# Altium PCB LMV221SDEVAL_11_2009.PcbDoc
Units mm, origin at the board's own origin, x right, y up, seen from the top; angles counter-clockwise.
Board outline 50.9 x 56.16 mm, 2 copper layers (Top Layer, Bottom Layer); 19 components, 8 nets, 54 pads, 66 vias.
Unrouted connection lines stored in the file: 8.
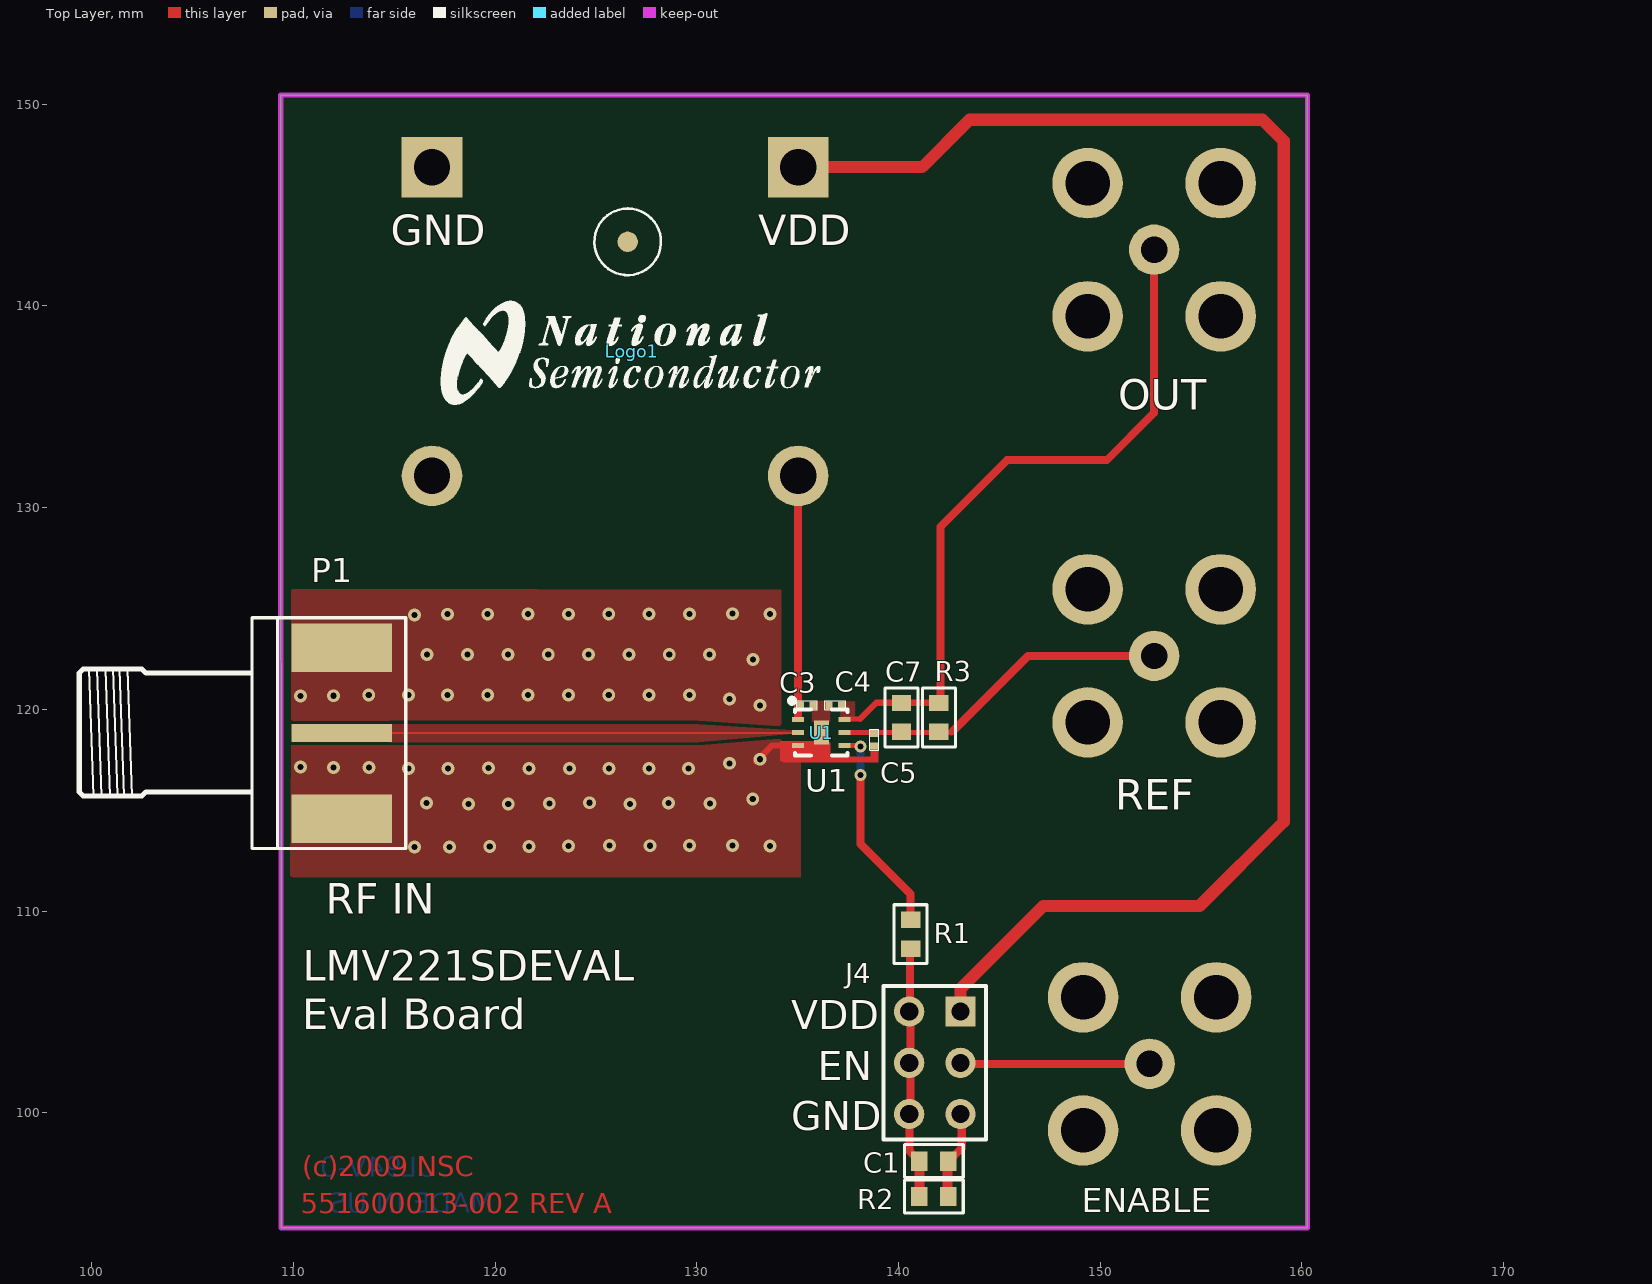
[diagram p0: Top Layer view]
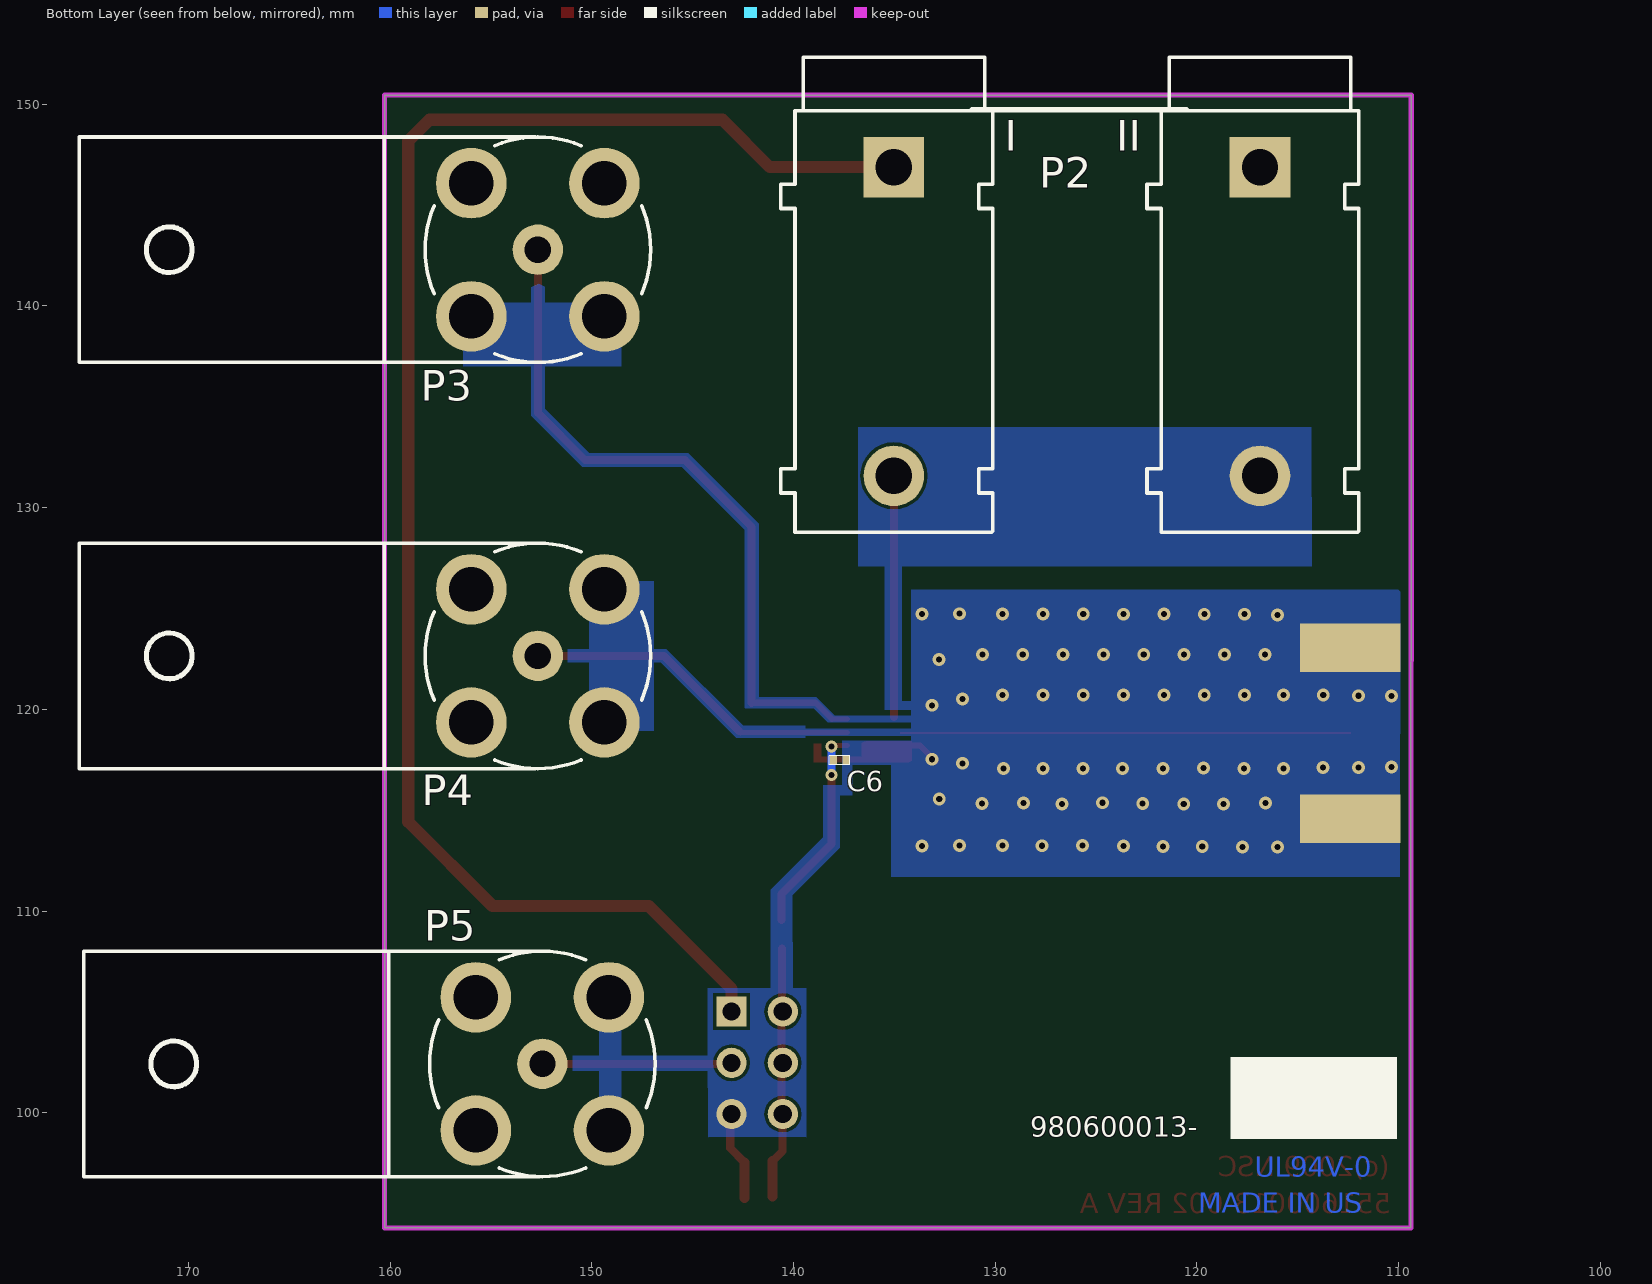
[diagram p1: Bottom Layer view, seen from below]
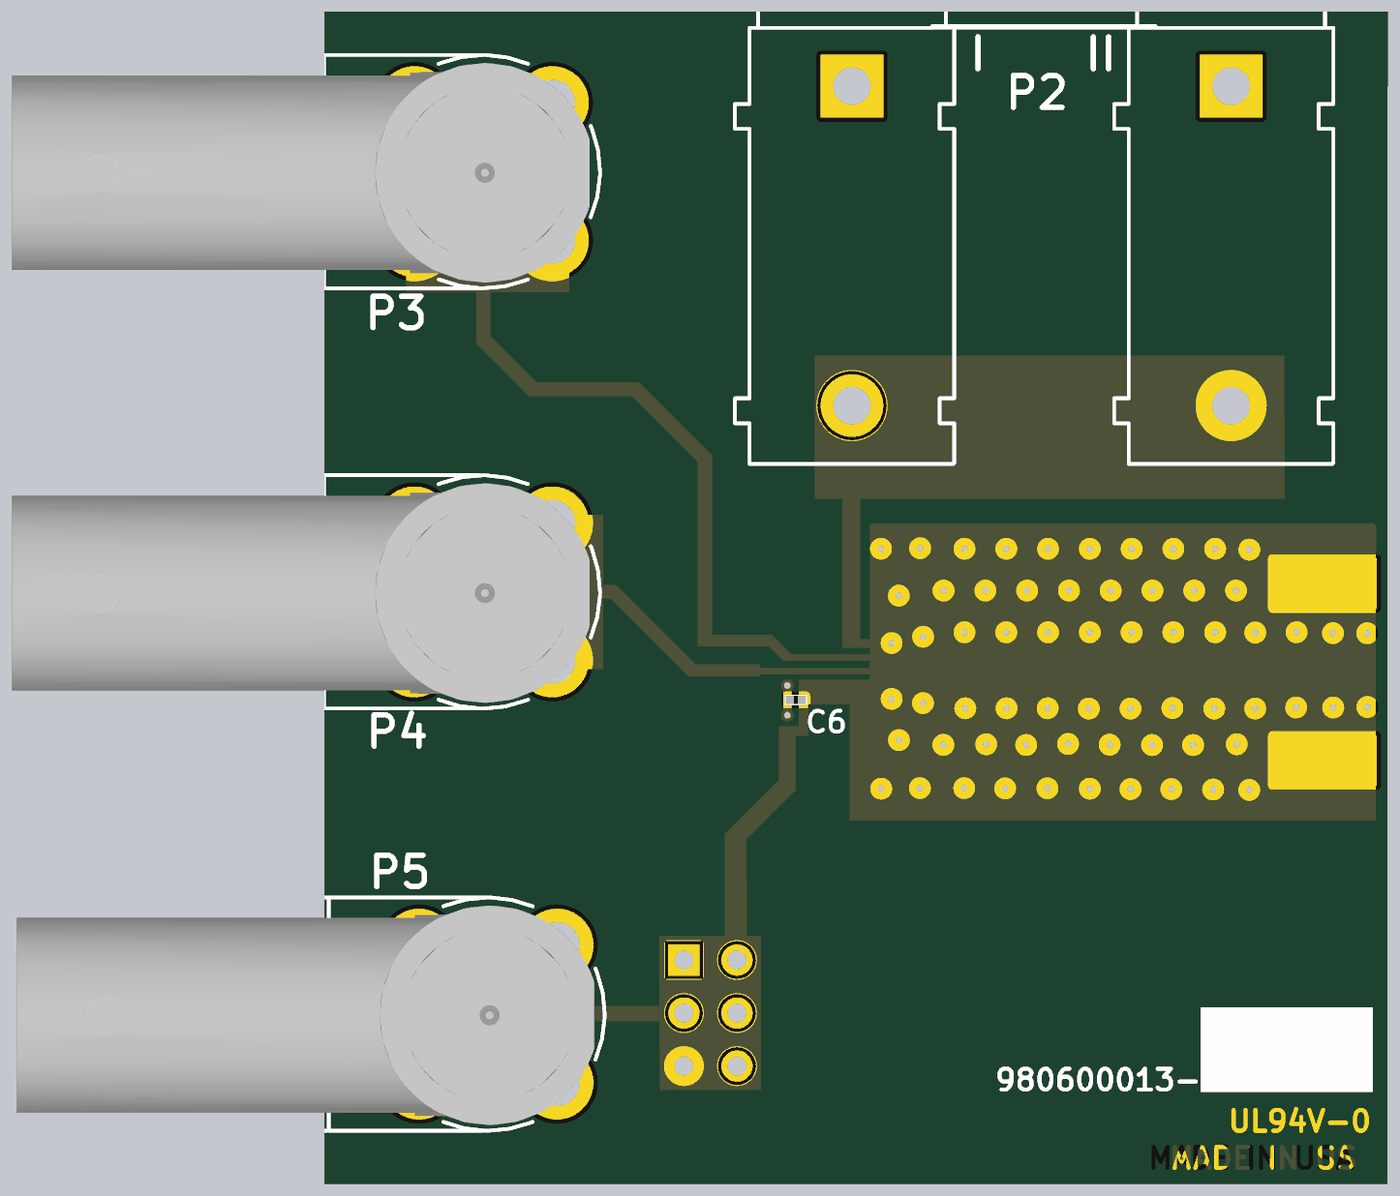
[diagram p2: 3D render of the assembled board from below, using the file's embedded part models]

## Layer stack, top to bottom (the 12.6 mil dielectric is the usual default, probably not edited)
Top Layer: signal copper 0.0356
Dielectric: core 0.32, FR-4, Dk 4.8
Bottom Layer: signal copper 0.0356

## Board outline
109.394,94.288 109.377,150.452 160.275,150.452 160.275,94.288

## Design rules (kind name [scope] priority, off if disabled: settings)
Clearance Clearance_4 [OnLayer('Mid-Layer 2') And (IsThruPin Or IsSMTPin Or IsWire) vs OnLayer('Mid-Layer 2') And (IsThruPin Or IsSMTPin Or IsWire Or IsVia)] p1: gap=0.01
Clearance Clearance_3 [OnLayer('Mid-Layer 1') And (IsThruPin Or IsSMTPin Or IsWire) vs OnLayer('Mid-Layer 1') And (IsThruPin Or IsSMTPin Or IsWire Or IsVia)] p2: gap=0.01
Clearance Clearance_2 [OnLayer('Bottom Layer') And (IsThruPin Or IsSMTPin Or IsWire) vs OnLayer('Bottom Layer') And (IsThruPin Or IsSMTPin Or IsWire Or IsVia)] p3: gap=0.15
Clearance Clearance_1 [OnLayer('Top Layer') And (IsThruPin Or IsSMTPin Or IsWire Or IsVia) vs OnLayer('Top Layer') And (IsThruPin Or IsSMTPin Or IsWire Or IsVia)] p4: gap=0.15
Clearance [All] p5: gap=0.152
PasteMaskExpansion [All] p1: expansion=0.051
PlaneConnect [All] p1: planeconnectstyle=Relief reliefexpansion=1 reliefentries=4 reliefconductorwidth=1 reliefairgap=0.8
PolygonConnect [All] p1: connectstyle=Direct reliefconductorwidth=0.254 reliefentries=4 polygonreliefangle="90 Angle"
RoomDefinition LMV221SDEVAL_11_2009 [InComponentClass('LMV221SDEVAL_11_2009')] p1: confinementstyle=ConfineIn formatcopy=TRUE lockcomponents=FALSE outline 161.404,93.156 168.804,93.156 168.804,115.308 161.404,115.308
RoutingVias [All] p1: holewidth=0.711 width=1.27 viastyle="Through Hole" minholewidth=0.711 minwidth=1.27 maxholewidth=0.711 maxwidth=1.27
SilkscreenOverComponentPads [All] p1: minsilkscreentomaskgap=0.254
SolderMaskExpansion [All] p1: expansion=0.203
TestPointUsage [All] p1: valid=0 allowmultiple=FALSE
Testpoint [All] p1: side=15 testpointundercomponent=TRUE minsize=1.016 maxsize=2.54 preferedsize=1.524 minholesize=0 maxholesize=1.016 preferedholesize=0.813 testpointgrid=0.025 style=1023 order=0123456789
Width Net_Width_1 [InNet('GND') Or InNet('N09047') Or InNet('N13699') Or InNet('N14327') Or InNet('N15309')] p1: maxlimit=2 minlimit=0.2 preferedwidth=0.2
Width [All] p2: maxlimit=2.007 minlimit=0.203 preferedwidth=0.203
21 further rules are at their usual default settings.

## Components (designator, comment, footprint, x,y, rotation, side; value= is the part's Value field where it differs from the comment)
C1 "10n" SM/RC_0603 141.75,97.6 r180 top
C3 "10p" C_SMD_201 135.475,120.2 r180 top
C4 "10p" C_SMD_201 136.85,120.2 r0 top
C5 "1p" C_SMD_201 138.8,118.5 r270 top
C6 "10p" C_SMD_201 137.7,117.475 r0 bottom
C7 "NC" SM/RC_0603 140.15,119.6 r90 top
I "571-0500" 571-0500 135.025,139.225 r270 bottom
II "571-0100" 571-0100 116.875,139.225 r270 bottom
J4 "Header 3x2" HDR2X3 141.8,102.475 r270 top
Logo1 "PCB Logo" Logo_Overlay_Medium 126.775,137.75 r0 top
P1 "RF IN" SMA-SIDE 112.4,118.825 r0 top
P3 "Vout" 5413631-2 152.674,142.784 r180 bottom
P4 "REF" 5413631-2 152.675,122.65 r180 bottom
P5 "Enable" 5413631-2 152.45,102.425 r180 bottom
R1 "100k" SM/RC_0603 140.6,108.85 r270 top
R2 "100k" SM/RC_0603 141.75,95.85 r180 top
R3 "NC" SM/RC_0603 142,119.6 r90 top
U1 "LLP6 LMV221" SDB06A 136.175,118.85 r270 top
? "Comment" Fiducial 126.575,143.175 r0 top

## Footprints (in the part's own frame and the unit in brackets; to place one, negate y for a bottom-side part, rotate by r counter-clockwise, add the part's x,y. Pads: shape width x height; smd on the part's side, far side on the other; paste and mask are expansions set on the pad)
571-0100 [mm] "Deltron Emcon recommended land pattern 2003-10-13"
  rect 3x3 hole 1.8: 1(-7.65,0)
  round 3 hole 1.8: 2(7.65,0)
  silkscreen extent -13.1,-5.6 10.45,4.9, body extent -13.04,-5.6 10.54,4.9, height 12.4
571-0500 [mm] "Deltron Emcon recommended land pattern 2003-10-13"
  rect 3x3 hole 1.8: 1(-7.65,0)
  round 3 hole 1.8: 2(7.65,0)
  silkscreen extent -13.1,-5.6 10.45,4.9, body extent -13.04,-5.6 10.54,4.9, height 12.4
5413631-2 [mm] "BNC footprint for Tyco_5413631"
  round 2.5 hole 1.3: 1(0,0)
  round 3.5 hole 2.2: 2(-3.3,3.3) 3(3.3,3.3) 4(3.3,-3.3) 5(-3.3,-3.3)
  Top Layer lines w0.05: 3.3,3.3 3.3,3.3
  silkscreen extent -22.73,-5.59 5.59,5.59, body extent -22.56,-5.27 5.08,5.16, height 11.66
C_SMD_201 [mm] "Chip Capacitor, 2-Leads, Body 0.6x0.3mm, IPC Medium Density"
  rect 0.35x0.4 smd: 1(-0.3,0) 2(0.325,0)
  silkscreen extent -0.5,-0.23 0.53,0.23, body extent -0.3,-0.16 0.31,0.15, height 0.02
Fiducial [mil]
  round 40 smd mask+40: 0(0,0)
  Top Overlay keep-out lines w5: 64.68,6.47 ccw(c0,0) 64.81,4.99
  silkscreen extent -65,-65 65,65
HDR2X3 [mm]
  rect 1.5x1.5 hole 0.9: 1(-2.54,1.27)
  round 1.5 hole 0.9: 2(-2.54,-1.27) 3(0,1.27) 4(0,-1.27) 5(2.54,1.27) 6(2.54,-1.27)
  silkscreen extent -3.81,-2.54 3.81,2.54
Logo_Overlay_Medium [mm]
  silkscreen extent -9.47,-2.64 9.35,2.51
SDB06A [mm] "LLP6 2.2x2.5x0.8  NO PULLBACK"
  rect 0.25x0.6 smd: 1(-0.65,-1.15) 2(0,-1.15) 3(0.65,-1.15) 4(0.65,1.15) 5(0,1.15) 6(-0.65,1.15)
  rect 1.2x0.75 smd: 7(0,0)
  silkscreen extent -1.7,-1.57 1.15,1.3, body extent -1.15,-1.3 1.15,1.3, height 0.8
SM/RC_0603 [mil]
  rect 32x38 smd: 1(-28,0) 2(28,0)
  silkscreen extent -58,-33 58,32
SMA-SIDE [mm]
  rect 5x0.9 smd: 1(0,0)
  rect 5x2.399 / inner round 1.524 / far side rect 5x2.399 all layers, no hole: 2(0,-4.25) 2(0,4.225)
  silkscreen extent -13.01,-5.71 3.17,5.72, body extent -13.03,-5.74 2.5,5.74, height 4

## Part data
C1 C3 C4 C5 C6 C7: library part "C smd"
I: "Standard Banana Jack, insulated, 10A, red"
II: "Standard Banana Jack, insulated, 10A, black"
Logo1: library part "NSC Logo", "National Semiconductor logo or worldmark"
P1: library part "SMA Right"
P3 P4 P5: library part 5413631-2, "Connector, TH, BNC Right angle, 50 Ohm gold"
R1 R2 R3: library part "R smd"

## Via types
v1: diameter 0.64, hole 0.3, Top Layer to Bottom Layer, 64 vias
v2: diameter 0.6, hole 0.3, Top Layer to Bottom Layer, tented both sides, 2 vias

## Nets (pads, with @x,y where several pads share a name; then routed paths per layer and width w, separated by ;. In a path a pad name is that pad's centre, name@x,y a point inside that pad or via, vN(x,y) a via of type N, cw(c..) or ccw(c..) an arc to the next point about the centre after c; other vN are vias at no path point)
GND: C1.1 C3.1 C4.1 C5.2 C6.1 II.1 II.2 J4.5 P1.2 P3.2 P3.3 P3.4 P3.5 P4.2 P4.3 P4.4 P4.5 P5.2 P5.3 P5.4 P5.5 R2.1 U1.3 U1.7 | length 6.9
  Top Layer w0.3: v1@132.931,117.403 133.741,118.213 U1.3@135.027,118.213 ; C1.1@142.439,97.522 142.425,97.535 C1.1@142.51,97.535 ; J4.5@143.133,99.897 J4.5@143.135,99.895
  Top Layer w0.4: C1.1@142.425,97.535 143.135,98.245 J4.5@143.135,99.895
  Top Layer w0.5: R2.1@142.425,95.785 C1.1@142.425,97.535
  other v1: 116.004,113.165 117.734,113.184 119.738,113.206 121.688,113.206 123.637,113.224 125.669,113.243 127.692,113.237 133.625,113.225 129.65,113.25 131.775,113.25 118.691,115.314 120.656,115.314 126.683,115.317 130.65,115.325 122.689,115.331 128.6,115.35 116.603,115.355 124.678,115.369 132.775,115.55 115.717,117.063 117.677,117.062 121.69,117.062 123.685,117.062 125.656,117.076 127.625,117.075 129.6,117.075 119.683,117.088 111.984,117.113 113.76,117.114 110.346,117.138 131.625,117.325 133.125,117.525 133.125,120.2 131.619,120.503 110.356,120.669 111.996,120.673 115.716,120.707 113.74,120.719 117.637,120.715 119.637,120.715 121.637,120.715 123.637,120.715 125.637,120.715 127.637,120.715 129.637,120.715 132.78,122.47 116.637,122.715 118.637,122.715 120.637,122.715 122.637,122.715 124.637,122.715 126.637,122.715 128.637,122.715 130.637,122.715 116,124.675 117.637,124.715 119.637,124.715 121.637,124.715 123.637,124.715 125.637,124.715 127.637,124.715 129.637,124.715 133.637,124.715 131.762,124.74
NetC1_2: C1.2 J4.2 J4.4 J4.6 R1.2 R2.2 | length 12.5
  Top Layer w0.4: R1.2@140.565,108.139 140.565,105.005 140.593,104.977 140.593,99.913 140.577,99.897 140.537,99.856 140.537,98.102 C1.2
  Top Layer w0.5: R2.2 C1.2
NetC3_2: C3.2 I.1 I.2 J4.1 U1.1 | length 91.8
  Top Layer w0.4: U1.1@135.027,119.625 I.2@135.027,131.575
  Top Layer w0.6: I.1 141.175,146.875 143.525,149.225 158.05,149.225 159.1,148.175 159.1,114.425 154.925,110.25 147.175,110.25 143.07,106.145 J4.1
NetC4_2: C4.2 C7.2 P3.1 R3.2 U1.6 | length 34.8
  Top Layer w0.25: U1.6@137.325,119.512 138.087,119.512
  Top Layer w0.3: 138.087,119.512 138.9,120.325 R3.2@142.075,120.325
  Top Layer w0.4: R3.2@142.075,120.325 142.075,129.05 145.375,132.35 150.325,132.35 152.674,134.699 P3.1
NetC5_1: C5.1 C7.1 P4.1 R3.1 U1.5 | length 17
  Top Layer w0.25: U1.5 142.625,118.85 142.7,118.925
  Top Layer w0.3: 142.638,118.863 142.7,118.925
  Top Layer w0.4: 142.7,118.925 146.425,122.65 P4.1
NetC6_2: C6.2 R1.1 U1.4 | length 10.5
  Top Layer w0.25: U1.4 138.084,118.2 v2(138.119,118.165)
  Top Layer w0.4: v2@138.097,118.213 138.1,118.216 138.119,118.197 v2(138.119,118.165) ; 138.119,113.331 v2(138.119,116.743) ; 138.119,113.331 140.6,110.85 R1.1
  Bottom Layer w0.4: v2(138.119,116.743) v2(138.119,116.743) v2(138.119,118.165) v2(138.119,118.165)
NetJ4_3: J4.3 P5.1 | length 9.4
  Top Layer w0.4: J4.3@143.07,102.425 P5.1 ; J4.3@143.12,102.437 J4.3@143.157,102.4
NetP1_1: P1.1 U1.2 | length 22.3
  Top Layer w0.1: P1.1 134.694,118.825
pads on no net: ?.0

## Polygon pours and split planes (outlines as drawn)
NetP1_1 on Top Layer "232" (solid, remove dead copper, pour order 1000): 114.738,118.375 127.621,118.375 127.604,119.27 114.738,119.27
GND on Top Layer "317" (solid, remove dead copper, pour order 1002): 109.846,111.672 110.468,111.672 116.559,111.68 135.164,111.68 135.164,117.857 134.192,117.857 134.192,125.931 109.901,125.982 109.901,125.595 109.901,120.679
NetP1_1 on Top Layer "220" (solid, remove dead copper, pour order 1001): 127.453,118.376 127.453,119.27 130.094,119.27 134.817,118.954 134.817,118.779 130.097,118.376
GND on Top Layer "Top Layer-GND" (hatched 90Degree grid 0 track 0.12, remove dead copper, pour order 1004): 135.75,120.375 136.575,120.375 136.575,119.4 135.75,119.4
NetC4_2 on Top Layer "331" (hatched 90Degree grid 0.1 track 0.1, pour order 1007): 137.139,119.623 137.825,119.623 137.825,120.375 137.139,120.375
GND on Bottom Layer "Bottom Layer-GND 4" (solid, pour order 1002): 142.425,120.075 142.425,128.9 145.55,132.025 150.475,132.025 153,134.55 153,137 156.375,137 156.375,140.15 153,140.15 153,141.425 152.325,141.425 152.325,140.15 148.55,140.15 148.55,137 152.325,137 152.325,134.9 150.125,132.7 145.225,132.7 141.725,129.2 141.725,120.075
GND on Bottom Layer "Bottom Layer-GND 1" (solid, remove dead copper, pour order 1001): 134.05,119.025 139.425,119.025 139.425,119.175 142.5,119.175 146.3,122.975 146.925,122.975 146.925,126.35 150.125,126.35 150.125,122.975 151.2,122.975 151.2,122.325 150.125,122.325 150.125,118.95 146.925,118.95 146.925,122.325 146.575,122.325 142.85,118.6 139.425,118.6 139.425,118.7 134.05,118.7
GND on Bottom Layer "Bottom Layer-GND" (solid): 144.1,102.825 148.55,102.825 148.55,105.025 148.575,105.05 149.625,105.05 149.625,102.825 150.95,102.825 150.95,102.075 149.625,102.075 149.625,99.875 148.55,99.875 148.55,102.075 144.1,102.075
GND on Bottom Layer "Bottom Layer-GND" (solid, pour order 1000): 144.225,98.775 144.25,103.675 144.25,106.175 141.775,106.175 141.125,106.175 141.125,111.05 138.525,113.65 138.525,116.225 137.575,116.225 137.575,118.45 134.05,118.45 134.05,117.25 137.1,117.25 137.1,115.75 137.7,115.75 137.7,113.15 140.075,110.775 140.05,106.175 139.375,106.175 139.375,101.225 139.375,98.775 141.775,98.8
GND on Bottom Layer "221" (solid, remove dead copper, pour order 1003): 134.502,111.695 135.15,111.695 135.15,117.894 134.173,117.894 134.173,125.93 109.932,125.93 109.953,111.695
GND on Bottom Layer "Bottom Layer-GND 3" (solid, pour order 1001): 134.1,119.675 137.95,119.675 138.875,120.6 142.4,120.6 142.4,120.05 139,120.05 138.3,119.35 134.1,119.35
GND on Bottom Layer "Bottom Layer-GND 2" (solid, pour order 1000): 133.95,119.975 135.475,119.975 135.475,127.375 134.625,127.375 134.625,120.4 133.975,120.4 133.975,120.425
GND on Bottom Layer "Bottom Layer-GND 5" (solid, pour order 1000): 114.325,133.975 136.8,133.975 136.8,127.1 114.3,127.1

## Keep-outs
Keep-Out Layer:
  the board outline again, w0.254

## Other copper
Top Layer:
  region net GND: 136.627,118.346 136.627,117.656 138.63,117.656 138.63,118.293 138.988,118.293 138.988,117.387 135.861,117.387 134.292,117.386 134.15,117.45 134.15,118.425 136.4,118.425 136.525,118.4
  text "(c)2009 NSC" at 110.45,96.85 h1
  text "551600013-002 REV A" at 110.375,95.025 h1
Bottom Layer:
  text "UL94V-0" at 117.125,96.825 h1
  text "MADE IN US" at 119.947,95.05 h1

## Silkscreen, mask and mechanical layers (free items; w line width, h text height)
Top Overlay:
  text "GND" at 114.825,143 h1.5
  text "VDD" at 133.05,143 h1.5
  text "OUT" at 150.9,134.85 h1.5
  text "U1" at 135.375,115.925 h1.12
  text "REF" at 150.75,115.025 h1.5
  text "LMV221SDEVAL" at 110.475,106.55 h1.5
  text "Eval Board" at 110.45,104.15 h1.5
  text "VDD" at 134.675,104.15 h1.43
  text "EN" at 136,101.6 h1.43
  text "GND" at 134.675,99.125 h1.43
  text "ENABLE" at 149.075,95.075 h1.2
Bottom Overlay:
  rectangle: 110.075,98.7 118.333,102.754
  lines w0.254: 120.525,149.725 131.15,149.725
  text "P2" at 127.825,145.85 h1.52
  text "980600013-" at 128.275,98.8 h1
Top Paste:
  text "881600013-002" at 110.15,82.2 h1
Bottom Paste:
  text "881600013-002" at 110.15,80.4 h1
Top Solder:
  text "(c)2007 NSC" at 110.45,96.85 h1
  text "551600013-001 REV 4" at 110.375,95.025 h1
  text "551600013-001 REV 4" at 110.375,95.025 h1
Bottom Solder:
  text "UL94V-0" at 117.125,96.825 h1
  text "UL94V-0" at 117.125,96.825 h1
  text "MADE IN USA" at 120.95,95.05 h1
  text "MADE IN USA" at 120.95,95.05 h1
Drill Drawing:
  lines w0.254: -0.127,-30.607 94.742,-30.607 ; -0.127,-30.48 -0.127,0 ; -0.127,0.127 94.742,0.127 ; 0,-25.4 94.615,-25.4 ; 0,-21.59 94.615,-21.59 ; 0,-17.78 94.615,-17.78 ; 0,-13.97 94.615,-13.97 ; 0,-10.16 94.615,-10.16 ; 0,-10.033 94.615,-10.033 ; 0,-5.08 94.615,-5.08 ; 0,-4.953 94.615,-4.953 ; 4.001,-24.13 5.271,-22.86 ; 4.001,-22.86 5.271,-24.13 ; 4.001,-12.065 5.271,-12.065 ; 4.635,-12.7 4.635,-11.43 ; 9.271,-25.4 9.271,-5.08 ; 9.398,-25.4 9.398,-5.08 ; 30.713,-25.4 30.713,-5.08 ; 51.202,-30.48 51.202,-5.08 ; 65.299,-30.48 65.299,-5.08 ; 94.742,-30.48 94.742,0 ; 4.001,-20.32 4.001,-19.05 ; 4.001,-20.32 5.271,-20.32 ; 4.001,-20.32 5.271,-19.05 ; 4.001,-19.05 5.271,-19.05 ; 4.001,-19.05 5.271,-20.32 ; 5.271,-20.32 5.271,-19.05 ; 0,-30.48 94.615,-30.48 94.615,0 0,0 0,-30.48 ; 4.001,-15.875 4.635,-15.24 5.271,-15.875 4.635,-16.51 4.001,-15.875
  text ".Legend" at 187.65,82.45 h2
  text ".Legend" at 0,0 h1.52

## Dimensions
160.275,94.288 to 109.394,94.288 on Mechanical 1 Outline
160.275,150.452 to 160.275,94.288 on Mechanical 1 Outline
